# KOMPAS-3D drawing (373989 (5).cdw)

Referenced files in C:\Documents and Settings\оля\Мои документы\Чертежи схемы установок\: На внутреннюю цилиндрическую поверхность.frw, На плоскости.frw, Направление усилия.frw
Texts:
  Текст на чертеже
  Размерные надписи
  Шероховатость
  Линия-выноска #1
  Линия-выноска #2
  Линия-выноска #3
  Отклонения формы и база
  Заголовок таблицы
  Ячейка таблицы
  Стрелка вида
  Обозначение изменения
  Фигурная скобка
  Номер узла
  Марка координационной оси
  VRCB
  Выносная надпись
  Обозначение узла
  Марка/позиционное обозначение с линией-выноской
  Марка/позиционное обозначение на линии
  Марка/позиционное обозначение без линии-выноски
  Упор
  Оля
  Изм. Лист № докум      Подпись      Дата
  Дублик
  Взамен
  Подпись
  Изм.
  Лист
  № докумен.
  Дата
  ТС-51.60240
  СК-4.54.60640
  Операция 20. Зубофрезерная
  Rz40
  Операция 25. Зубошевинговальная
Dimensions and other numbers on the sheet: 7; 3; 108; 1:1; 2; 4; 5; 6; 8; 9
